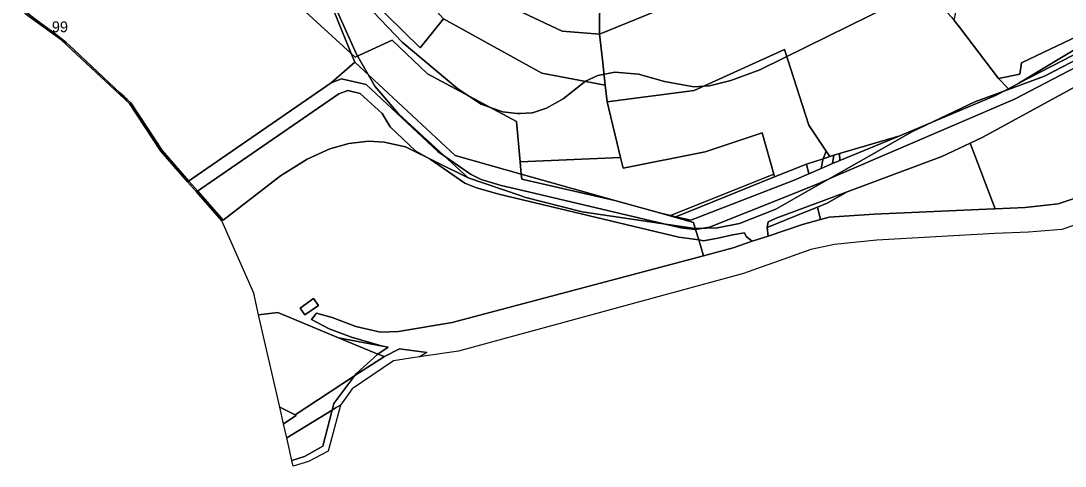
# Model space of a CAD drawing. Extents: x -535894 to -532834, y -1165802 to -1163645.
# Drawn here: x -535230.1 to -534748.9, y -1165662.7 to -1165457.3 of the extents above; entities that cross this region are included whole.
import ezdxf

# ---------------------------------------------------------------- set-up
doc = ezdxf.new("R2010")
doc.units = 0
for name, color, linetype in [('95610013', 7, 'Continuous'), ('95630013', 7, 'Continuous'), ('95640013', 7, 'Continuous'), ('95660013', 7, 'Continuous')]:
    doc.layers.add(name, color=color, linetype=linetype)

msp = doc.modelspace()

# ---------------------------------------------------------------- linework, layer by layer
at = {"layer": '95610013'}
for points in [[(-535045.46, -1165379.26), (-535035.57, -1165371.22), (-534991.19, -1165417.39), (-534976.33, -1165433.85), (-534971.78, -1165438.88), (-534963.24, -1165444.04), (-534963.38, -1165463.4), (-534980.62, -1165462.08), (-535021.86, -1165442.54), (-535066.38, -1165395.21)], [(-535071.39, -1165401.58), (-535066.38, -1165395.21), (-535021.86, -1165442.54), (-534980.62, -1165462.08), (-534963.38, -1165463.4), (-534962.06, -1165475.26), (-534960.76, -1165486.97), (-534989.98, -1165481.49), (-535035.38, -1165456.43), (-535077.63, -1165409.51)], [(-534777.14, -1165399.85), (-534774.44, -1165402.06), (-534708.8, -1165446.03), (-534706.72, -1165447.2), (-534726.22, -1165454.44), (-534731.16, -1165459.74), (-534737, -1165466.01), (-534739.65, -1165462.65), (-534768.94, -1165476.68), (-534769.67, -1165481.85), (-534779.55, -1165483.95), (-534797.58, -1165460.25), (-534800.02, -1165457.14), (-534797.86, -1165446.44), (-534791.04, -1165427.36), (-534790.14, -1165428.15), (-534783.92, -1165413.27)], [(-535092.6, -1165423.96), (-535077.63, -1165409.51), (-535035.38, -1165456.43), (-535046.07, -1165469.78)], [(-534918.48, -1165416.99), (-534895.63, -1165410.85), (-534867.49, -1165451.44), (-534870.05, -1165452.66), (-534891.46, -1165433.95), (-534963.38, -1165463.4), (-534963.24, -1165444.04), (-534971.78, -1165438.88), (-534976.33, -1165433.85), (-534946.88, -1165427.7), (-534950.64, -1165422.73)], [(-535102.15, -1165432.54), (-535096.21, -1165427.21), (-535077.85, -1165472.41), (-535109.7, -1165443.14), (-535107.08, -1165437.55)], [(-535096.21, -1165427.21), (-535092.6, -1165423.96), (-535046.07, -1165469.78), (-535035.38, -1165456.43), (-534989.98, -1165481.49), (-534960.76, -1165486.97), (-534959.91, -1165494.58), (-534953.71, -1165520.27), (-535000.04, -1165522.28), (-535001.7, -1165503.8), (-535042.71, -1165481.75), (-535059.01, -1165466.27), (-535076.09, -1165474.03), (-535077.85, -1165472.41)], [(-534822.96, -1165431.91), (-534801.16, -1165455.68), (-534800.02, -1165457.14), (-534797.58, -1165460.25), (-534779.55, -1165483.95), (-534775.01, -1165488.64), (-534780.88, -1165491.68), (-534825.02, -1165510.26), (-534852.85, -1165518.48), (-534855.37, -1165519.3), (-534857.32, -1165519.92), (-534858.97, -1165517.45), (-534866.97, -1165505.4), (-534878.14, -1165470.55), (-534919.78, -1165489.38), (-534959.91, -1165494.58), (-534960.76, -1165486.97), (-534962.06, -1165475.26), (-534963.38, -1165463.4), (-534891.46, -1165433.95), (-534870.05, -1165452.66), (-534867.49, -1165451.44), (-534859.91, -1165447.81), (-534826.73, -1165433.38)], [(-534728.78, -1165464.21), (-534730.58, -1165465.6), (-534770.13, -1165486.11), (-534737, -1165466.01), (-534731.16, -1165459.74)], [(-534739.65, -1165462.65), (-534737, -1165466.01), (-534770.13, -1165486.11), (-534775.01, -1165488.64), (-534779.55, -1165483.95), (-534769.67, -1165481.85), (-534768.94, -1165476.68)], [(-534919.78, -1165489.38), (-534878.14, -1165470.55), (-534866.97, -1165505.4), (-534858.97, -1165517.45), (-534860.3, -1165520.88), (-534868.01, -1165523.35), (-534882.77, -1165529.3), (-534883.15, -1165527.96), (-534888.5, -1165509.02), (-534914.81, -1165517.68), (-534952.5, -1165525.21), (-534953.71, -1165520.27), (-534959.91, -1165494.58)], [(-534787.1, -1165511.18), (-534722.56, -1165475.88), (-534702.49, -1165513.54), (-534734.15, -1165535.63), (-534752.11, -1165541.71), (-534767.34, -1165543.34), (-534781.05, -1165543.94), (-534792.57, -1165513.75)], [(-534914.81, -1165517.68), (-534888.5, -1165509.02), (-534883.15, -1165527.96), (-534930.71, -1165547.06), (-534935.79, -1165545.88), (-534956.4, -1165540.09), (-534999.52, -1165528), (-535000.04, -1165522.28), (-534953.71, -1165520.27), (-534952.5, -1165525.21)], [(-534852.85, -1165518.48), (-534825.02, -1165510.26), (-534852.75, -1165521.74)], [(-534805.71, -1165519.94), (-534792.57, -1165513.75), (-534781.05, -1165543.94), (-534781.63, -1165543.97), (-534836.88, -1165546.52), (-534857.57, -1165547.81), (-534861.62, -1165548.94), (-534863.04, -1165543.26), (-534858.59, -1165541.43), (-534849.32, -1165536.17)], [(-534857.32, -1165519.92), (-534855.37, -1165519.3), (-534856.09, -1165523.12), (-534861.32, -1165525.37), (-534860.51, -1165521.43), (-534860.3, -1165520.88)], [(-534858.97, -1165517.45), (-534857.32, -1165519.92), (-534860.3, -1165520.88)], [(-534855.37, -1165519.3), (-534852.85, -1165518.48), (-534852.75, -1165521.74), (-534856.09, -1165523.12)], [(-534868.01, -1165523.35), (-534866.9, -1165527.79), (-534873.72, -1165530.76), (-534921.41, -1165549.22), (-534928.28, -1165547.62), (-534882.77, -1165529.3)], [(-534860.51, -1165521.43), (-534861.32, -1165525.37), (-534866.9, -1165527.79), (-534868.01, -1165523.35), (-534860.3, -1165520.88)], [(-534999.52, -1165528), (-534956.4, -1165540.09), (-534999.31, -1165530.27)], [(-534883.15, -1165527.96), (-534882.77, -1165529.3), (-534928.28, -1165547.62), (-534930.71, -1165547.06)], [(-534858.59, -1165541.43), (-534863.04, -1165543.26), (-534868.03, -1165545.3), (-534886.11, -1165552.64), (-534885.76, -1165550.05), (-534882.03, -1165548.34), (-534849.32, -1165536.17)], [(-534868.03, -1165545.3), (-534863.04, -1165543.26), (-534861.62, -1165548.94), (-534869.82, -1165551.23), (-534885.69, -1165556.54), (-534886.11, -1165552.64)], [(-535120.55, -1165592.9), (-535111.76, -1165591.74), (-535083.74, -1165603.43), (-535065.59, -1165611), (-535075.3, -1165619.81), (-535076.16, -1165620.93), (-535076.36, -1165621.07), (-535103.74, -1165639.03), (-535110.85, -1165635.43)], [(-535083.74, -1165603.43), (-535063.44, -1165607.34), (-535060.83, -1165607.77), (-535065.59, -1165611)], [(-535065.59, -1165611), (-535062.6, -1165612.04), (-535076.16, -1165620.93), (-535075.3, -1165619.81)], [(-535084.78, -1165635.66), (-535082.82, -1165634.47), (-535088.47, -1165655.7), (-535097.63, -1165660.52), (-535104.63, -1165662.66), (-535104.92, -1165661.39), (-535105.21, -1165660.12), (-535099.44, -1165658.24), (-535090.9, -1165653.48), (-535086.73, -1165636.86)], [(-535107.61, -1165649.63), (-535086.73, -1165636.86), (-535090.9, -1165653.48), (-535099.44, -1165658.24), (-535105.21, -1165660.12)]]:
    msp.add_lwpolyline(points, close=True, dxfattribs=at)
at = {"layer": '95630013'}
msp.add_lwpolyline([(-534728.46, -1165546.03), (-534750.37, -1165553.57), (-534765.78, -1165554.79), (-534781.3, -1165555.36), (-534835.68, -1165558.38), (-534855.2, -1165560.47), (-534865.99, -1165562.72), (-534882.85, -1165568.74), (-534888.88, -1165570.88), (-534897.05, -1165573.8), (-535028.46, -1165609.66), (-535046.55, -1165612.31), (-535043.09, -1165610.19), (-535055.57, -1165608.62), (-535062.6, -1165612.04), (-535065.59, -1165611), (-535060.83, -1165607.77), (-535063.44, -1165607.34), (-535077.76, -1165603.24), (-535088.09, -1165599.33), (-535096.22, -1165595.01), (-535093.94, -1165592.1), (-535086.71, -1165594.09), (-535075.77, -1165598.23), (-535064.42, -1165600.94), (-535056.11, -1165600.58), (-535031.28, -1165596.42), (-534915.56, -1165565.61), (-534901.88, -1165561.94), (-534893.04, -1165558.98), (-534885.69, -1165556.54), (-534869.82, -1165551.23), (-534861.62, -1165548.94), (-534857.57, -1165547.81), (-534836.88, -1165546.52), (-534781.63, -1165543.97), (-534781.05, -1165543.94), (-534767.34, -1165543.34), (-534752.11, -1165541.71), (-534734.15, -1165535.63)], dxfattribs=at)
for points in [[(-535055.57, -1165608.62), (-535043.09, -1165610.19), (-535046.55, -1165612.31), (-535058.4, -1165614.04), (-535077.5, -1165627.02), (-535082.82, -1165634.47), (-535084.78, -1165635.66), (-535086.73, -1165636.86), (-535085.96, -1165633.8), (-535076.16, -1165620.93), (-535062.6, -1165612.04)], [(-535076.16, -1165620.93), (-535085.96, -1165633.8), (-535086.73, -1165636.86), (-535107.61, -1165649.63), (-535109.1, -1165643.08), (-535103.18, -1165639.32), (-535103.74, -1165639.03), (-535076.36, -1165621.07)]]:
    msp.add_lwpolyline(points, close=True, dxfattribs=at)
at = {"layer": '95640013'}
for points in [[(-535131.97, -1165385.19), (-535105.08, -1165427.18), (-535102.66, -1165428.89), (-535103.85, -1165430.74), (-535111.02, -1165441.92), (-535109.7, -1165443.14), (-535077.85, -1165472.41), (-535076.26, -1165476.34), (-535087.18, -1165485.86), (-535153.29, -1165531.56), (-535165.68, -1165517.45), (-535180.07, -1165495.46), (-535211.33, -1165466.2), (-535227.94, -1165454.25), (-535230.12, -1165447.22), (-535227.28, -1165430.67), (-535216.3, -1165378.85), (-535186.38, -1165424.39)], [(-535076.09, -1165474.03), (-535059.01, -1165466.27), (-535042.71, -1165481.75), (-535001.7, -1165503.8), (-535000.04, -1165522.28), (-534999.52, -1165528), (-535029.98, -1165519.47), (-535076.26, -1165476.34), (-535077.85, -1165472.41)], [(-535082.4, -1165484.03), (-535087.18, -1165485.86), (-535076.26, -1165476.34), (-535029.98, -1165519.47), (-534999.52, -1165528), (-534999.31, -1165530.27), (-534956.4, -1165540.09), (-534935.79, -1165545.88), (-534920.17, -1165550.26), (-534919.2, -1165553.5), (-534919.44, -1165553.53), (-534926.03, -1165552.84), (-534998.84, -1165535.55), (-535008.78, -1165533.19), (-535017.91, -1165530.5), (-535022.95, -1165527.99), (-535037.98, -1165517.6), (-535070.93, -1165486.65)], [(-535082.4, -1165484.03), (-535070.93, -1165486.65), (-535037.98, -1165517.6), (-535022.95, -1165527.99), (-535017.91, -1165530.5), (-535008.78, -1165533.19), (-534998.84, -1165535.55), (-534926.03, -1165552.84), (-534919.44, -1165553.53), (-534919.2, -1165553.5), (-534917.74, -1165558.37), (-534926.87, -1165557.06), (-535009.77, -1165537.3), (-535020.09, -1165534.38), (-535025.58, -1165532.21), (-535041.43, -1165521.13), (-535048.04, -1165517.37), (-535059.98, -1165506.16), (-535063.55, -1165500.03), (-535073.7, -1165490.85), (-535079.48, -1165489.46), (-535083.65, -1165491.01), (-535149.25, -1165536.15), (-535153.29, -1165531.56), (-535087.18, -1165485.86)], [(-535079.48, -1165489.46), (-535073.7, -1165490.85), (-535063.55, -1165500.03), (-535059.98, -1165506.16), (-535048.04, -1165517.37), (-535041.43, -1165521.13), (-535025.58, -1165532.21), (-535020.09, -1165534.38), (-535009.77, -1165537.3), (-534926.87, -1165557.06), (-534917.74, -1165558.37), (-534915.56, -1165565.61), (-535031.28, -1165596.42), (-535056.11, -1165600.58), (-535064.42, -1165600.94), (-535075.77, -1165598.23), (-535086.71, -1165594.09), (-535093.94, -1165592.1), (-535096.22, -1165595.01), (-535088.09, -1165599.33), (-535077.76, -1165603.24), (-535063.44, -1165607.34), (-535083.74, -1165603.43), (-535111.76, -1165591.74), (-535120.55, -1165592.9), (-535122.82, -1165582.96), (-535137.55, -1165549.48), (-535149.25, -1165536.15), (-535083.65, -1165491.01)], [(-534902.07, -1165555.96), (-534896.68, -1165555.06), (-534895.8, -1165556.74), (-534893.04, -1165558.98), (-534901.88, -1165561.94), (-534915.56, -1165565.61), (-534917.74, -1165558.37), (-534915.46, -1165558.7), (-534908.91, -1165557.54)], [(-535095.3, -1165585.33), (-535092.97, -1165588.51), (-535099.28, -1165592.83), (-535101.36, -1165589.79)], [(-535095.3, -1165585.33), (-535101.36, -1165589.79), (-535099.28, -1165592.83), (-535092.97, -1165588.51)], [(-535103.74, -1165639.03), (-535103.18, -1165639.32), (-535109.1, -1165643.08), (-535110.85, -1165635.43)]]:
    msp.add_lwpolyline(points, close=True, dxfattribs=at)
for points in [[(-534601.41, -1165404.16), (-534772.12, -1165493.42), (-534853.75, -1165528.43), (-534862.8, -1165532.4), (-534877.24, -1165538.36), (-534912.68, -1165552.42), (-534919.2, -1165553.5), (-534920.17, -1165550.26), (-534935.79, -1165545.88), (-534930.71, -1165547.06), (-534928.28, -1165547.62), (-534921.41, -1165549.22), (-534873.72, -1165530.76), (-534866.9, -1165527.79), (-534861.32, -1165525.37), (-534856.09, -1165523.12), (-534852.75, -1165521.74), (-534825.02, -1165510.26), (-534780.88, -1165491.68), (-534775.01, -1165488.64), (-534770.13, -1165486.11), (-534730.58, -1165465.6)], [(-534722.56, -1165475.88), (-534787.1, -1165511.18), (-534792.57, -1165513.75), (-534805.71, -1165519.94), (-534849.32, -1165536.17), (-534882.03, -1165548.34), (-534885.76, -1165550.05), (-534886.11, -1165552.64), (-534885.69, -1165556.54), (-534893.04, -1165558.98), (-534895.8, -1165556.74), (-534896.68, -1165555.06), (-534902.07, -1165555.96), (-534908.91, -1165557.54), (-534915.46, -1165558.7), (-534917.74, -1165558.37), (-534919.2, -1165553.5), (-534912.68, -1165552.42), (-534877.24, -1165538.36), (-534862.8, -1165532.4), (-534853.75, -1165528.43), (-534772.12, -1165493.42), (-534601.41, -1165404.16)]]:
    msp.add_lwpolyline(points, dxfattribs=at)
at = {"layer": '95660013'}
msp.add_lwpolyline([(-535197.513, -1165478.818), (-535197.667, -1165478.989), (-535211.33, -1165466.2), (-535227.94, -1165454.25), (-535230.12, -1165447.22), (-535229.937, -1165446.154), (-535229.697, -1165446.939), (-535228.059, -1165452.29), (-535227.757, -1165452.533), (-535227.491, -1165453.394), (-535221.739, -1165457.976), (-535214.364, -1165463.282), (-535209.32, -1165467.33), (-535205.939, -1165470.375), (-535197.241, -1165478.516)], close=True, dxfattribs=at)
for points in [[(-535087.04, -1165446.54), (-535075.396, -1165472.696), (-535066.97, -1165487.48), (-535056.14, -1165500.22), (-535023.96, -1165529.68), (-535052.79, -1165515.35), (-535062.67, -1165513.2), (-535069.908, -1165512.831), (-535077.531, -1165513.752), (-535078.92, -1165513.92), (-535087.68, -1165516.3), (-535098.19, -1165521.08), (-535110.5, -1165528.74), (-535136.922, -1165549.195), (-535148.621, -1165535.871), (-535152.657, -1165531.277), (-535165.053, -1165517.172), (-535179.439, -1165495.178), (-535181.153, -1165493.572), (-535182.335, -1165492.465), (-535182.542, -1165492.191), (-535184.454, -1165490.483), (-535197.241, -1165478.516), (-535205.939, -1165470.375), (-535209.32, -1165467.33), (-535214.364, -1165463.282), (-535221.739, -1165457.976), (-535227.491, -1165453.394)], [(-534738.22, -1165472.34), (-534758.29, -1165482.861), (-534772.475, -1165488.055), (-534790.46, -1165494.641), (-534819.223, -1165508.375), (-534853.06, -1165527.61), (-534867.072, -1165535.575), (-534882.21, -1165544.18), (-534898.979, -1165550.694), (-534909.12, -1165552.78), (-534919.471, -1165553.024), (-534935.09, -1165550.71), (-534971.389, -1165545.333), (-534998, -1165538.6), (-534999.621, -1165538.043), (-535000, -1165537.912), (-535023.96, -1165529.68), (-535056.14, -1165500.22), (-535066.97, -1165487.48), (-535075.396, -1165472.696), (-535087.04, -1165446.54)], [(-534820.011, -1165445.538), (-534868.03, -1165469.28), (-534889.61, -1165479.95), (-534902.91, -1165484.89), (-534912.71, -1165487.28), (-534920.03, -1165487.67), (-534933.49, -1165485.29), (-534945.52, -1165481.86), (-534956.43, -1165480.98), (-534964.23, -1165482.5), (-534969.97, -1165485.13), (-534980.24, -1165493.329), (-534987.888, -1165497.572), (-534994.317, -1165499.666), (-534994.455, -1165499.711), (-535000, -1165500.024), (-535001.35, -1165500.101), (-535008.2, -1165499.22), (-535017.91, -1165495.8), (-535028.739, -1165488.63), (-535054.39, -1165467.13), (-535074.14, -1165446.26)], [(-535074.14, -1165446.26), (-535054.39, -1165467.13), (-535028.739, -1165488.63), (-535017.91, -1165495.8), (-535008.2, -1165499.22), (-535001.35, -1165500.101), (-535000, -1165500.024), (-534994.455, -1165499.711), (-534994.317, -1165499.666), (-534987.888, -1165497.572), (-534980.24, -1165493.329), (-534969.97, -1165485.13), (-534964.23, -1165482.5), (-534956.43, -1165480.98), (-534945.52, -1165481.86), (-534933.49, -1165485.29), (-534920.03, -1165487.67), (-534912.71, -1165487.28), (-534902.91, -1165484.89), (-534889.61, -1165479.95), (-534868.03, -1165469.28), (-534820.011, -1165445.538)], [(-534728.46, -1165546.03), (-534750.37, -1165553.57), (-534765.78, -1165554.79), (-534781.3, -1165555.36), (-534835.68, -1165558.38), (-534855.2, -1165560.47), (-534865.99, -1165562.72), (-534882.85, -1165568.74), (-534888.88, -1165570.88), (-534897.05, -1165573.8), (-535028.46, -1165609.66), (-535046.55, -1165612.31), (-535058.4, -1165614.04), (-535077.5, -1165627.02), (-535082.82, -1165634.47), (-535088.47, -1165655.7), (-535097.63, -1165660.52), (-535104.63, -1165662.66), (-535104.92, -1165661.39), (-535105.21, -1165660.12), (-535107.61, -1165649.63), (-535109.1, -1165643.08), (-535110.85, -1165635.43), (-535120.55, -1165592.9), (-535122.82, -1165582.96), (-535137.55, -1165549.48), (-535149.25, -1165536.15), (-535153.29, -1165531.56), (-535165.68, -1165517.45), (-535180.07, -1165495.46), (-535197.667, -1165478.989), (-535197.513, -1165478.818), (-535197.241, -1165478.516), (-535184.454, -1165490.483), (-535182.542, -1165492.191), (-535182.335, -1165492.465), (-535181.153, -1165493.572), (-535179.439, -1165495.178), (-535165.053, -1165517.172), (-535152.657, -1165531.277), (-535148.621, -1165535.871), (-535136.922, -1165549.195), (-535110.5, -1165528.74), (-535098.19, -1165521.08), (-535087.68, -1165516.3), (-535078.92, -1165513.92), (-535077.531, -1165513.752), (-535069.908, -1165512.831), (-535062.67, -1165513.2), (-535052.79, -1165515.35), (-535023.96, -1165529.68), (-535000, -1165537.912), (-534999.621, -1165538.043), (-534998, -1165538.6), (-534971.389, -1165545.333), (-534935.09, -1165550.71), (-534919.471, -1165553.024), (-534909.12, -1165552.78), (-534898.979, -1165550.694), (-534882.21, -1165544.18), (-534867.072, -1165535.575), (-534853.06, -1165527.61), (-534819.223, -1165508.375), (-534790.46, -1165494.641), (-534772.475, -1165488.055), (-534758.29, -1165482.861), (-534738.22, -1165472.34)]]:
    msp.add_lwpolyline(points, dxfattribs=at)

# ---------------------------------------------------------------- texts
msp.add_text('99', height=5, rotation=0, dxfattribs=at).set_placement((-535215.863, -1165462.572))

doc.saveas('drawing.dxf')
